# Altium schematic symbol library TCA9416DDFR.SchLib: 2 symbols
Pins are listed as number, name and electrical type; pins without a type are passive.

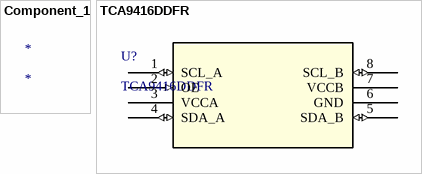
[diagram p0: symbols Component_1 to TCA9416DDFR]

## Component_1
designator *

## TCA9416DDFR
designator U?
IC TRANSLATOR BIDIR TSOT23-8; Manufacturer: Texas Instruments
footprint SOT_16DDFR_TEX
pins: 1 SCL_A (io), 2 OE (in), 3 VCCA (power), 4 SDA_A (io), 5 SDA_B (io), 6 GND (power), 7 VCCB (power), 8 SCL_B (io)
